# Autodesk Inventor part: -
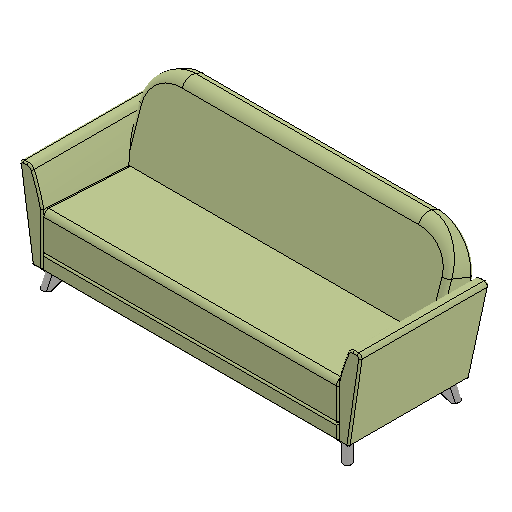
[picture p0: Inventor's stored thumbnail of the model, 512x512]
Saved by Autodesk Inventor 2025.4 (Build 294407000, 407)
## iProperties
Created: 2026-05
Part Number: -
Material: Generic
Description: 3-SEATER
Document SubType Name: Modeling
Designer: Brian.Thangei
Density: 1 g/cm^3
Appearance: Default
Project: HENLEY
Sending System: SolidWorks 2026
Preprocessor: SwSTEP 2.0
Title: Henley 3-Seater.STEP
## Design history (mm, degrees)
feature "NONE"
feature "NONE:1"
feature "NONE:2"
feature "NONE:3"
feature "NONE:4"
feature "NONE:5"
feature "NONE:6"
feature "NONE:7"
feature "NONE:8"
workplane "Work Plane1"
workplane "Work Plane2"
workplane "Work Plane3"
workplane "Work Plane4"
workplane "Work Plane5"
workplane "Work Plane6"
node "BASE"
node "ARM"
node "SEAT"
node "FOOT"
node "FOOT2"
node "BACK"
node "FOOT3"
node "ARM2"
node "FOOT4"
